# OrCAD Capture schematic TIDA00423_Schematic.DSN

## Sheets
1 PAGE2: size B; title: TIDA00423 High-Speed Front-End for PCIe Gen-3 Cards; rev: B; note: TIDA00423 Page 2
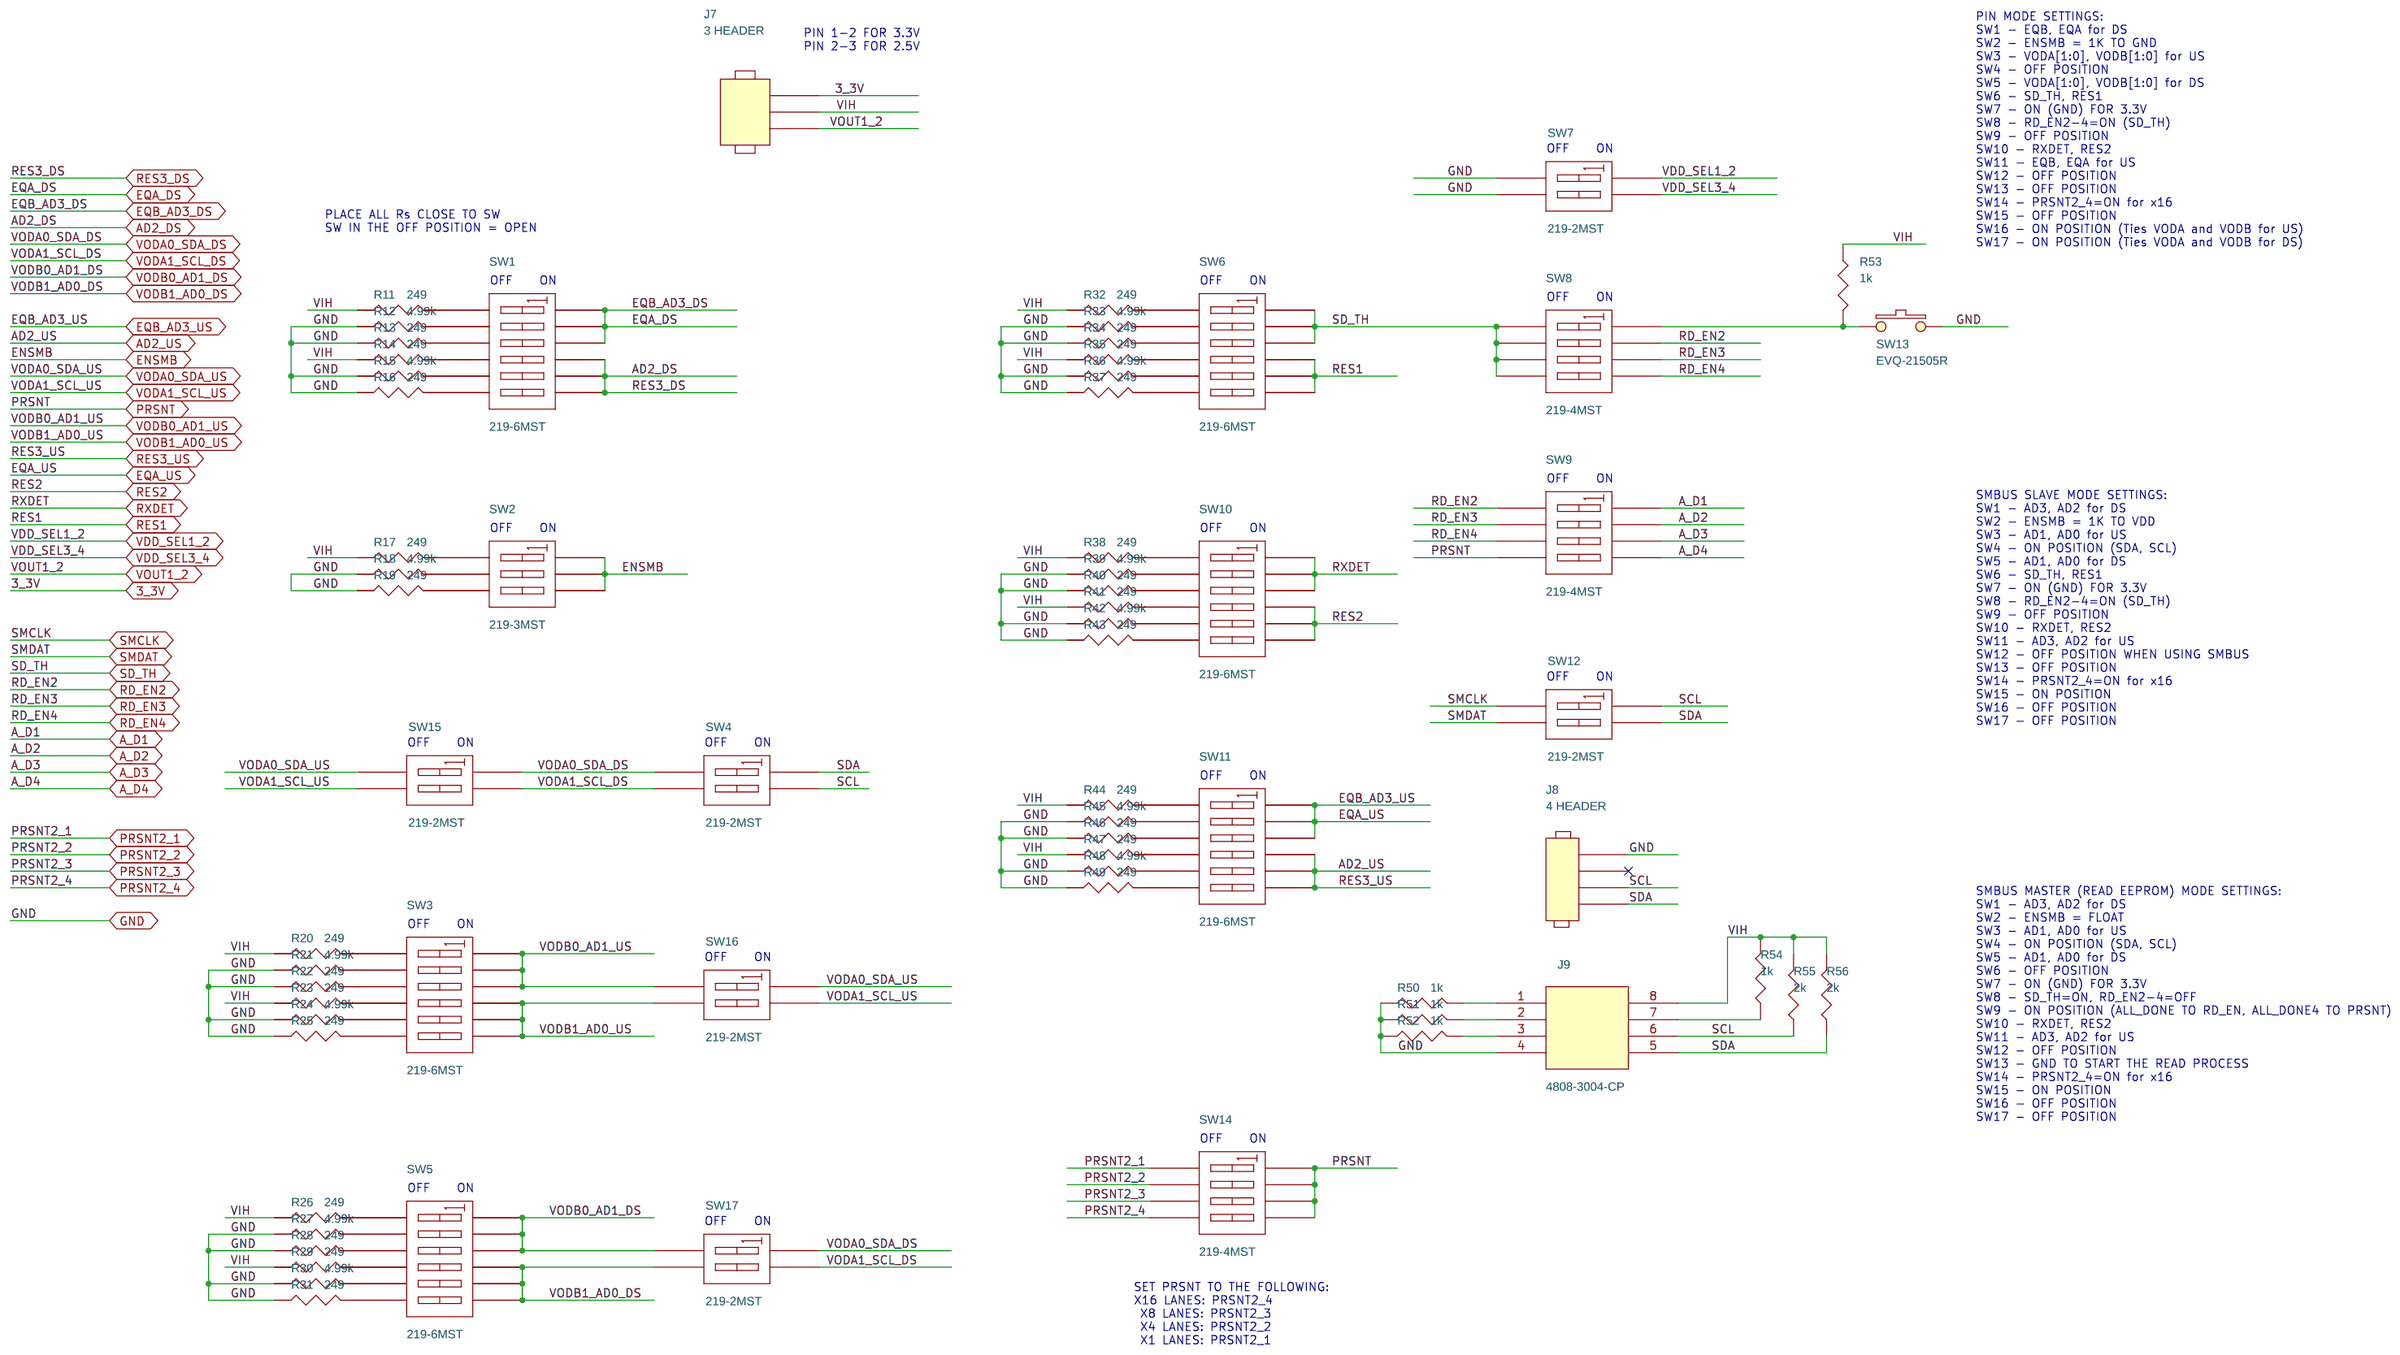
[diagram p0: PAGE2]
2 PAGE1: size B; note: TIDA00423 Page 1
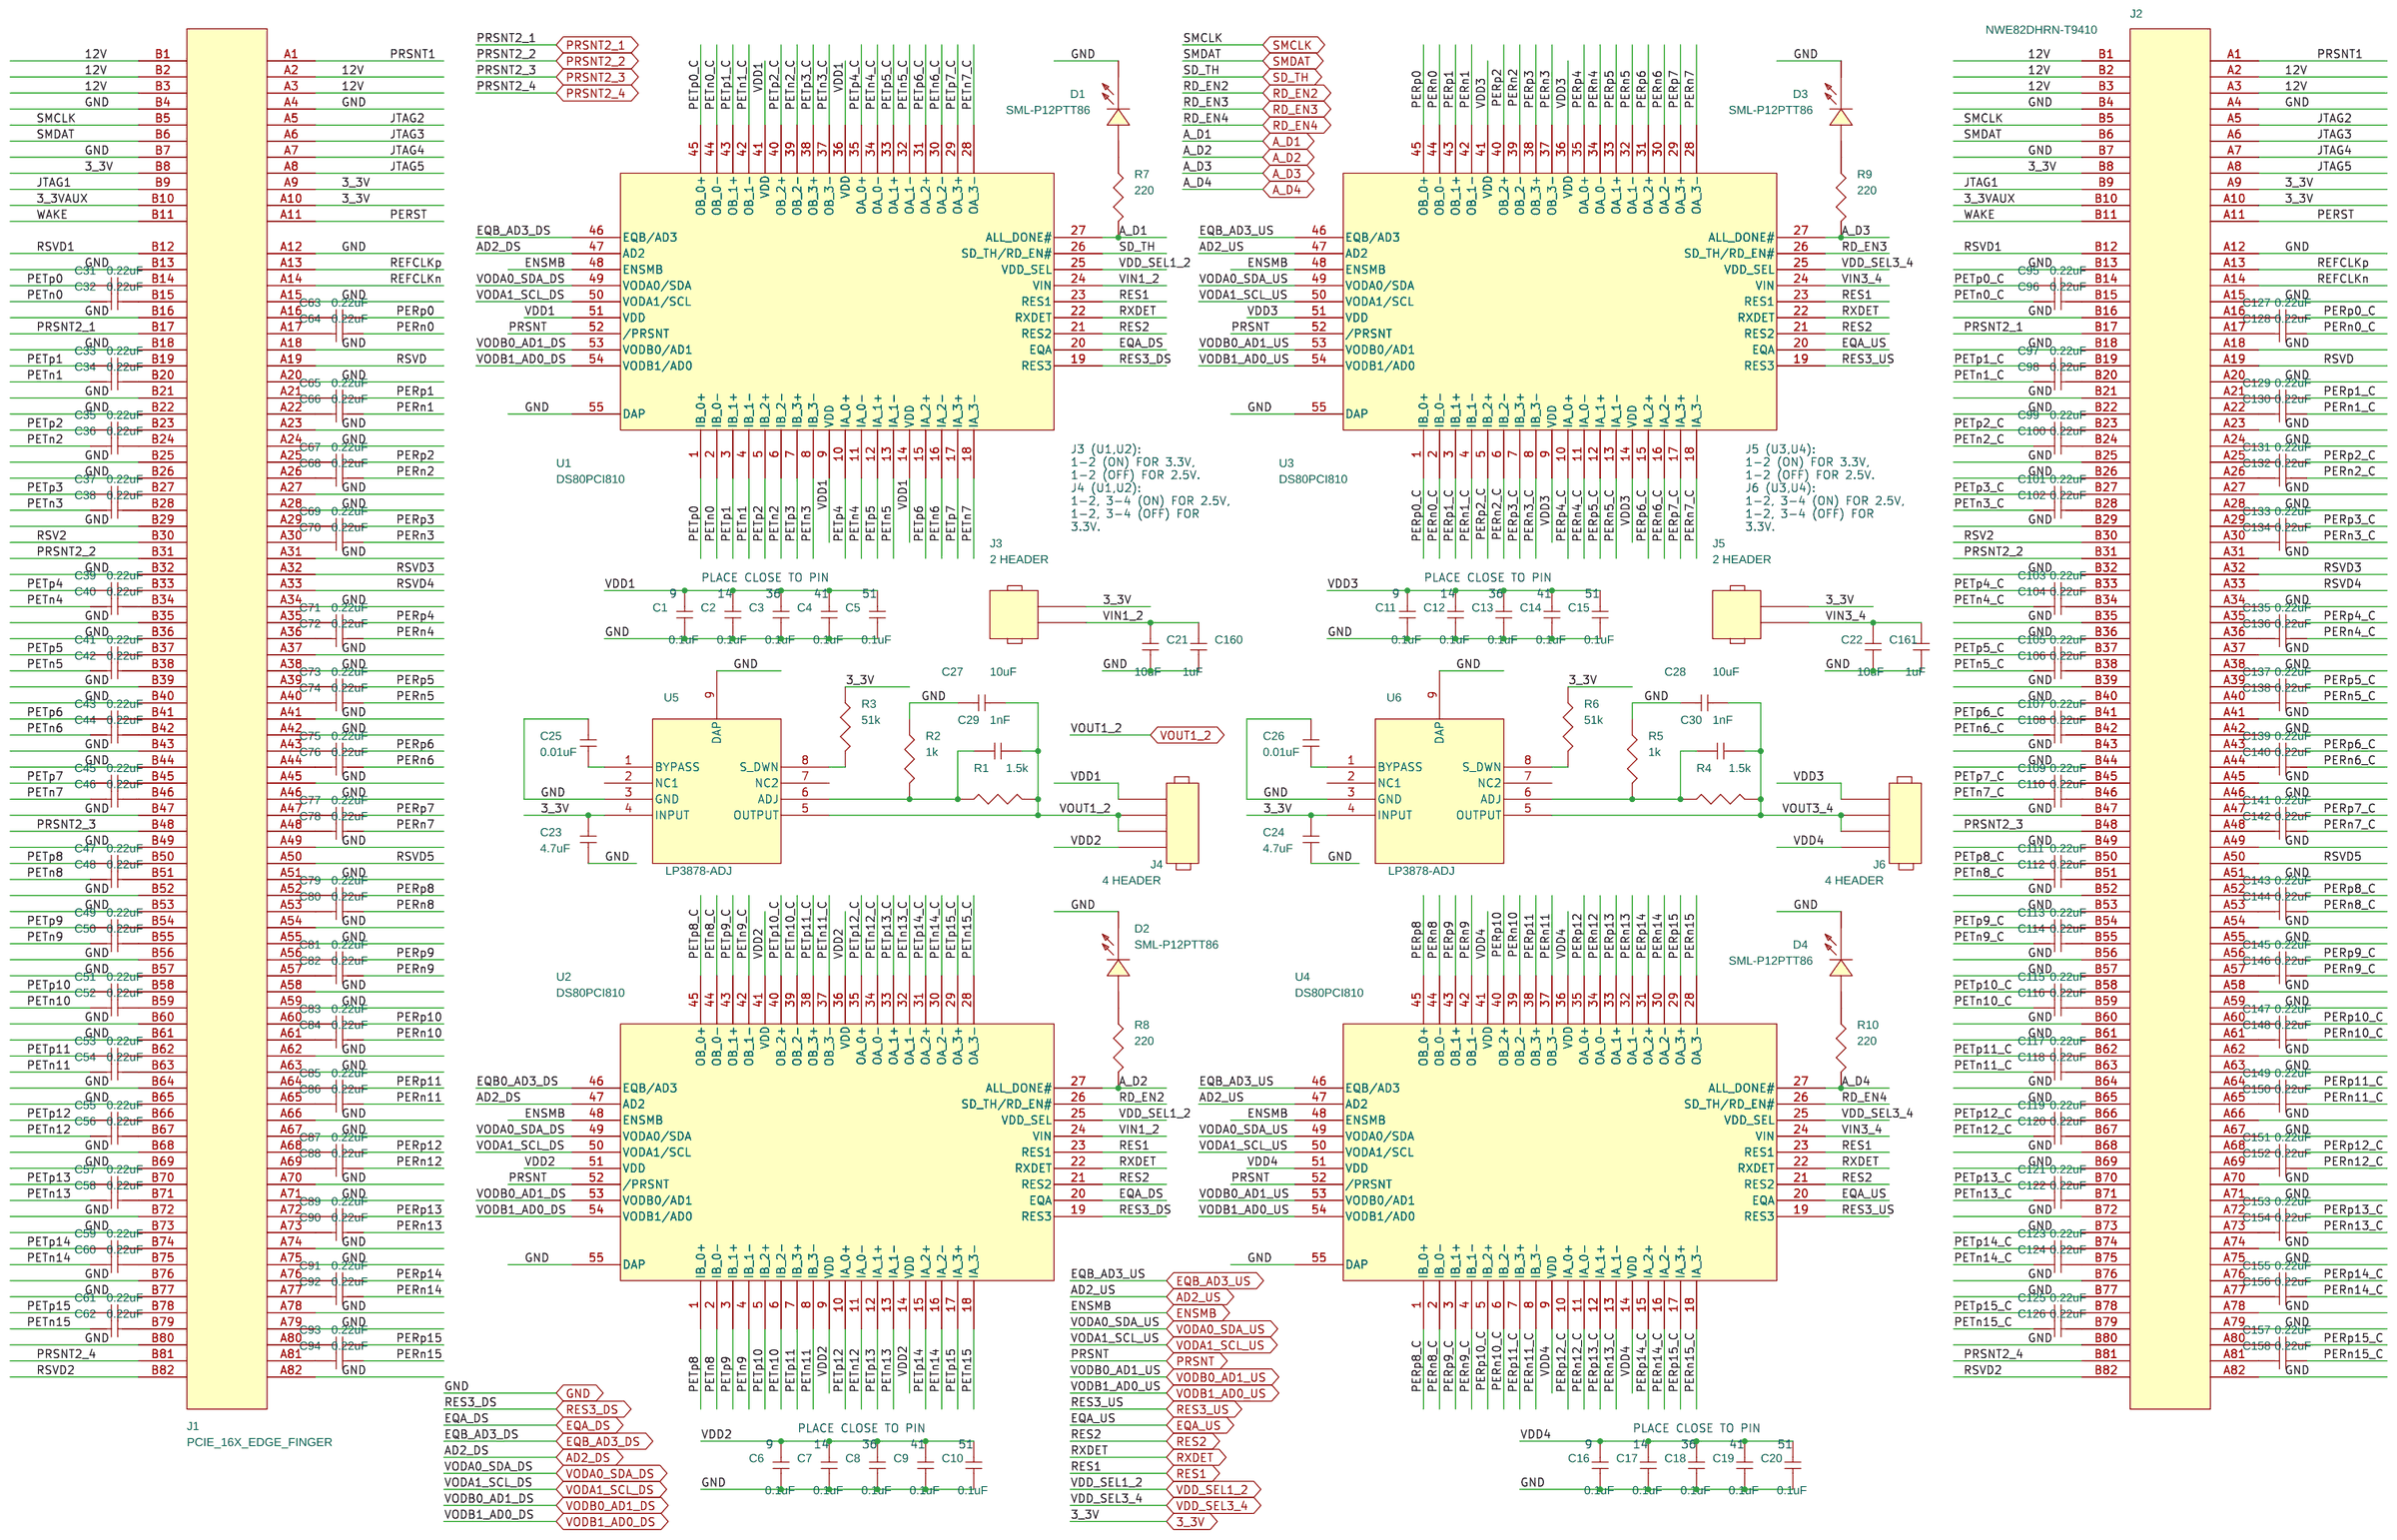
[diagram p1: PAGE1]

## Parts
sheet PAGE1
C1  0.1uF  [0201]
C2  0.1uF  [0201]
C3  0.1uF  [0201]
C4  0.1uF  [0201]
C5  0.1uF  [0201]
C6  0.1uF  [0201]
C7  0.1uF  [0201]
C8  0.1uF  [0201]
C9  0.1uF  [0201]
C10  0.1uF  [0201]
C11  0.1uF  [0201]
C12  0.1uF  [0201]
C13  0.1uF  [0201]
C14  0.1uF  [0201]
C15  0.1uF  [0201]
C16  0.1uF  [0201]
C17  0.1uF  [0201]
C18  0.1uF  [0201]
C19  0.1uF  [0201]
C20  0.1uF  [0201]
C21  10uF  [0603]
C22  10uF  [0603]
C23  4.7uF  [0402]
C24  4.7uF  [0402]
C25  0.01uF  [0402]
C26  0.01uF  [0402]
C27  10uF  [0603]
C28  10uF  [0603]
C29  1nF  [0201]
C30  1nF  [0201]
C31  0.22uF  [0201]
C32  0.22uF  [0201]
C33  0.22uF  [0201]
C34  0.22uF  [0201]
C35  0.22uF  [0201]
C36  0.22uF  [0201]
C37  0.22uF  [0201]
C38  0.22uF  [0201]
C39  0.22uF  [0201]
C40  0.22uF  [0201]
C41  0.22uF  [0201]
C42  0.22uF  [0201]
C43  0.22uF  [0201]
C44  0.22uF  [0201]
C45  0.22uF  [0201]
C46  0.22uF  [0201]
C47  0.22uF  [0201]
C48  0.22uF  [0201]
C49  0.22uF  [0201]
C50  0.22uF  [0201]
C51  0.22uF  [0201]
C52  0.22uF  [0201]
C53  0.22uF  [0201]
C54  0.22uF  [0201]
C55  0.22uF  [0201]
C56  0.22uF  [0201]
C57  0.22uF  [0201]
C58  0.22uF  [0201]
C59  0.22uF  [0201]
C60  0.22uF  [0201]
C61  0.22uF  [0201]
C62  0.22uF  [0201]
C63  0.22uF  [0201]
C64  0.22uF  [0201]
C65  0.22uF  [0201]
C66  0.22uF  [0201]
C67  0.22uF  [0201]
C68  0.22uF  [0201]
C69  0.22uF  [0201]
C70  0.22uF  [0201]
C71  0.22uF  [0201]
C72  0.22uF  [0201]
C73  0.22uF  [0201]
C74  0.22uF  [0201]
C75  0.22uF  [0201]
C76  0.22uF  [0201]
C77  0.22uF  [0201]
C78  0.22uF  [0201]
C79  0.22uF  [0201]
C80  0.22uF  [0201]
C81  0.22uF  [0201]
C82  0.22uF  [0201]
C83  0.22uF  [0201]
C84  0.22uF  [0201]
C85  0.22uF  [0201]
C86  0.22uF  [0201]
C87  0.22uF  [0201]
C88  0.22uF  [0201]
C89  0.22uF  [0201]
C90  0.22uF  [0201]
C91  0.22uF  [0201]
C92  0.22uF  [0201]
C93  0.22uF  [0201]
C94  0.22uF  [0201]
C95  0.22uF  [0201]
C96  0.22uF  [0201]
C97  0.22uF  [0201]
C98  0.22uF  [0201]
C99  0.22uF  [0201]
C100  0.22uF  [0201]
C101  0.22uF  [0201]
C102  0.22uF  [0201]
C103  0.22uF  [0201]
C104  0.22uF  [0201]
C105  0.22uF  [0201]
C106  0.22uF  [0201]
C107  0.22uF  [0201]
C108  0.22uF  [0201]
C109  0.22uF  [0201]
C110  0.22uF  [0201]
C111  0.22uF  [0201]
C112  0.22uF  [0201]
C113  0.22uF  [0201]
C114  0.22uF  [0201]
C115  0.22uF  [0201]
C116  0.22uF  [0201]
C117  0.22uF  [0201]
C118  0.22uF  [0201]
C119  0.22uF  [0201]
C120  0.22uF  [0201]
C121  0.22uF  [0201]
C122  0.22uF  [0201]
C123  0.22uF  [0201]
C124  0.22uF  [0201]
C125  0.22uF  [0201]
C126  0.22uF  [0201]
C127  0.22uF  [0201]
C128  0.22uF  [0201]
C129  0.22uF  [0201]
C130  0.22uF  [0201]
C131  0.22uF  [0201]
C132  0.22uF  [0201]
C133  0.22uF  [0201]
C134  0.22uF  [0201]
C135  0.22uF  [0201]
C136  0.22uF  [0201]
C137  0.22uF  [0201]
C138  0.22uF  [0201]
C139  0.22uF  [0201]
C140  0.22uF  [0201]
C141  0.22uF  [0201]
C142  0.22uF  [0201]
C143  0.22uF  [0201]
C144  0.22uF  [0201]
C145  0.22uF  [0201]
C146  0.22uF  [0201]
C147  0.22uF  [0201]
C148  0.22uF  [0201]
C149  0.22uF  [0201]
C150  0.22uF  [0201]
C151  0.22uF  [0201]
C152  0.22uF  [0201]
C153  0.22uF  [0201]
C154  0.22uF  [0201]
C155  0.22uF  [0201]
C156  0.22uF  [0201]
C157  0.22uF  [0201]
C158  0.22uF  [0201]
C160  1uF  [0402]
C161  1uF  [0402]
D1  SML-P12PTT86  [0402]
D2  SML-P12PTT86  [0402]
D3  SML-P12PTT86  [0402]
D4  SML-P12PTT86  [0402]
J1  PCIE_16X_EDGE_FINGER  [PCIE_16X_EDGE_FINGER]
J2  NWE82DHRN-T9410  [NWE82DHRN-T9410]
J3  2 HEADER  [2_HEADER]
J4  4 HEADER  [4_HEADER]
J5  2 HEADER  [2_HEADER]
J6  4 HEADER  [4_HEADER]
R1  1.5k  [0402]
R2  1k  [0402]
R3  51k  [0402]
R4  1.5k  [0402]
R5  1k  [0402]
R6  51k  [0402]
R7  220  [0402]
R8  220  [0402]
R9  220  [0402]
R10  220  [0402]
U1  DS80PCI810  [54_LLP]
U2  DS80PCI810  [54_LLP]
U3  DS80PCI810  [54_LLP]
U4  DS80PCI810  [54_LLP]
U5  LP3878-ADJ  [PSOP-8]
U6  LP3878-ADJ  [PSOP-8]
sheet PAGE2
J7  3 HEADER  [3_HEADER]
J8  4 HEADER  [4_HEADER]
J9  4808-3004-CP  [DIP8]
R11  249  [0402]
R12  4.99k  [0402]
R13  249  [0402]
R14  249  [0402]
R15  4.99k  [0402]
R16  249  [0402]
R17  249  [0402]
R18  4.99k  [0402]
R19  249  [0402]
R20  249  [0402]
R21  4.99k  [0402]
R22  249  [0402]
R23  249  [0402]
R24  4.99k  [0402]
R25  249  [0402]
R26  249  [0402]
R27  4.99k  [0402]
R28  249  [0402]
R29  249  [0402]
R30  4.99k  [0402]
R31  249  [0402]
R32  249  [0402]
R33  4.99k  [0402]
R34  249  [0402]
R35  249  [0402]
R36  4.99k  [0402]
R37  249  [0402]
R38  249  [0402]
R39  4.99k  [0402]
R40  249  [0402]
R41  249  [0402]
R42  4.99k  [0402]
R43  249  [0402]
R44  249  [0402]
R45  4.99k  [0402]
R46  249  [0402]
R47  249  [0402]
R48  4.99k  [0402]
R49  249  [0402]
R50  1k  [0402]
R51  1k  [0402]
R52  1k  [0402]
R53  1k  [0402]
R54  1k  [0402]
R55  2k  [0402]
R56  2k  [0402]
SW1  219-6MST  [219-6MST]
SW2  219-3MST  [219-3MST]
SW3  219-6MST  [219-6MST]
SW4  219-2MST  [219-2MST]
SW5  219-6MST  [219-6MST]
SW6  219-6MST  [219-6MST]
SW7  219-2MST  [219-2MST]
SW8  219-4MST  [219-4MST]
SW9  219-4MST  [219-4MST]
SW10  219-6MST  [219-6MST]
SW11  219-6MST  [219-6MST]
SW12  219-2MST  [219-2MST]
SW13  EVQ-21505R  [EVQ-21505R]
SW14  219-4MST  [219-4MST]
SW15  219-2MST  [219-2MST]
SW16  219-2MST  [219-2MST]
SW17  219-2MST  [219-2MST]

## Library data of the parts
C1-C158 = C_0
C160 C161 = C
D1-D4 = 1091QM_0
J1 = PCIE_16X_EDGE_FINGER
J2 = NWE82DHRN-T9410
J3 J5 = HEADER_2
J4 J6 J8 = 4_HEADER
R1-R6 R53-R56 = RESISTOR_SM
R7-R10 = R_0: Power: 1/16W; Tolerance: 5%
U1-U4 = DS80PCI800_0
U5 U6 = LP3878-ADJ_0
J7 = HEADER_3
J9 = DIP8_SOCKET
R11-R52 = RESISTOR
SW1 SW3 SW5 SW6 SW10 SW11 = SW_DIP-6_SM
SW2 = SW_DIP-3_SM
SW4 SW7 SW12 SW15-SW17 = SW_DIP-2_SM
SW8 SW9 SW14 = SW_DIP-4_SM
SW13 = SW_PUSHBUTTON-SPST

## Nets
12V: J1.A2 J1.A3 J1.B1 J1.B2 J1.B3 J2.A2 J2.A3 J2.B1 J2.B2 J2.B3
GND: C1.1 C2.1 C3.1 C4.1 C5.1 C6.1 C7.1 C8.1 C9.1 C10.1 C11.1 C12.1 C13.1 C14.1 C15.1 C16.1 C17.1 C18.1 C19.1 C20.1 C21.1 C22.1 C23.1 C24.1 C25.2 C26.2 C27.2 C28.2 C160.1 C161.1 D1.1(CATHODE) D2.1(CATHODE) D3.1(CATHODE) D4.1(CATHODE) J1.A4 J1.A12 J1.A15 J1.A18 J1.A20 J1.A23 J1.A24 J1.A27 J1.A28 J1.A31 J1.A34 J1.A37 J1.A38 J1.A41 J1.A42 J1.A45 J1.A46 J1.A49 J1.A51 J1.A54 J1.A55 J1.A58 J1.A59 J1.A62 J1.A63 J1.A66 J1.A67 J1.A70 J1.A71 J1.A74 J1.A75 J1.A78 J1.A79 J1.A82 J1.B4 J1.B7 J1.B13 J1.B16 J1.B18 J1.B21 J1.B22 J1.B25 J1.B26 J1.B29 J1.B32 J1.B35 J1.B36 J1.B39 J1.B40 J1.B43 J1.B44 J1.B47 J1.B49 J1.B52 J1.B53 J1.B56 J1.B57 J1.B60 J1.B61 J1.B64 J1.B65 J1.B68 J1.B69 J1.B72 J1.B73 J1.B76 J1.B77 J1.B80 J2.A4 J2.A12 J2.A15 J2.A18 J2.A20 J2.A23 J2.A24 J2.A27 J2.A28 J2.A31 J2.A34 J2.A37 J2.A38 J2.A41 J2.A42 J2.A45 J2.A46 J2.A49 J2.A51 J2.A54 J2.A55 J2.A58 J2.A59 J2.A62 J2.A63 J2.A66 J2.A67 J2.A70 J2.A71 J2.A74 J2.A75 J2.A78 J2.A79 J2.A82 J2.B4 J2.B7 J2.B13 J2.B16 J2.B18 J2.B21 J2.B22 J2.B25 J2.B26 J2.B29 J2.B32 J2.B35 J2.B36 J2.B39 J2.B40 J2.B43 J2.B44 J2.B47 J2.B49 J2.B52 J2.B53 J2.B56 J2.B57 J2.B60 J2.B61 J2.B64 J2.B65 J2.B68 J2.B69 J2.B72 J2.B73 J2.B76 J2.B77 J2.B80 J8.1 J9.4 R2.1 R5.1 R12.1 R13.1 R15.1 R16.1 R18.1 R19.1 R21.1 R22.1 R24.1 R25.1 R27.1 R28.1 R30.1 R31.1 R33.1 R34.1 R36.1 R37.1 R39.1 R40.1 R42.1 R43.1 R45.1 R46.1 R48.1 R49.1 R50.1 R51.1 R52.1 SW7.1(A1) SW7.2(A2) SW13.2 U1.55(DAP) U2.55(DAP) U3.55(DAP) U4.55(DAP) U5.3(GND) U5.9(DAP) U6.3(GND) U6.9(DAP)
VDD1: C1.2 C2.2 C3.2 C4.2 C5.2 J4.1 U1.9(VDD) U1.14(VDD) U1.36(VDD) U1.41(VDD) U1.51(VDD)
VDD2: C6.2 C7.2 C8.2 C9.2 C10.2 J4.4 U2.9(VDD) U2.14(VDD) U2.36(VDD) U2.41(VDD) U2.51(VDD)
VDD3: C11.2 C12.2 C13.2 C14.2 C15.2 J6.1 U3.9(VDD) U3.14(VDD) U3.36(VDD) U3.41(VDD) U3.51(VDD)
VDD4: C16.2 C17.2 C18.2 C19.2 C20.2 J6.4 U4.9(VDD) U4.14(VDD) U4.36(VDD) U4.41(VDD) U4.51(VDD)
VDD_SEL1_2: SW7.4(B1) U1.25(VDD_SEL) U2.25(VDD_SEL)
VDD_SEL3_4: SW7.3(B2) U3.25(VDD_SEL) U4.25(VDD_SEL)
VIN1_2: C21.2 C160.2 J3.2 U1.24(VIN) U2.24(VIN)
VIN3_4: C22.2 C161.2 J5.2 U3.24(VIN) U4.24(VIN)
3_3V: C23.2 C24.2 J1.A9 J1.A10 J1.B8 J2.A9 J2.A10 J2.B8 J3.1 J5.1 J7.1 R3.1 R6.1 U5.4(INPUT) U6.4(INPUT)
3_3VAUX: J1.B10 J2.B10
A_D1: R7.2 SW9.8(B1) U1.27(ALL_DONE#)
A_D2: R8.2 SW9.7(B2) U2.27(ALL_DONE#)
A_D3: R9.2 SW9.6(B3) U3.27(ALL_DONE#)
A_D4: R10.2 SW9.5(B4) U4.27(ALL_DONE#)
AD2_DS: SW1.7(B6) SW1.8(B5) SW1.9(B4) U1.19(RES3) U1.47(AD2) U2.19(RES3) U2.47(AD2)
AD2_US: SW11.7(B6) SW11.8(B5) SW11.9(B4) U3.19(RES3) U3.47(AD2) U4.19(RES3) U4.47(AD2)
ENSMB: SW2.4(B3) SW2.5(B2) SW2.6(B1) U1.48(ENSMB) U2.48(ENSMB) U3.48(ENSMB) U4.48(ENSMB)
EQA_DS: SW1.10(B3) SW1.11(B2) SW1.12(B1) U1.20(EQA) U1.46(EQB/AD3) U2.20(EQA)
EQA_US: SW11.10(B3) SW11.11(B2) SW11.12(B1) U3.20(EQA) U3.46(EQB/AD3) U4.20(EQA) U4.46(EQB/AD3)
EQB0_AD3_DS: U2.46(EQB/AD3)
JTAG1: J1.B9 J2.B9
JTAG2: J1.A5 J2.A5
JTAG3: J1.A6 J2.A6
JTAG4: J1.A7 J2.A7
JTAG5: J1.A8 J2.A8
PERn0: C64.1 U3.44(OB_0-)
PERn0_C: C128.1 U3.2(IB_0-)
PERn1: C66.1 U3.42(OB_1-)
PERn1_C: C130.1 U3.4(IB_1-)
PERn2: C68.1 U3.39(OB_2-)
PERn2_C: C132.1 U3.6(IB_2-)
PERn3: C70.1 U3.37(OB_3-)
PERn3_C: C134.1 U3.8(IB_3-)
PERn4: C72.1 U3.34(OA_0-)
PERn4_C: C136.1 U3.11(IA_0-)
PERn5: C74.1 U3.32(OA_1-)
PERn5_C: C138.1 U3.13(IA_1-)
PERn6: C76.1 U3.30(OA_2-)
PERn6_C: C140.1 U3.16(IA_2-)
PERn7: C78.1 U3.28(OA_3-)
PERn7_C: C142.1 U3.18(IA_3-)
PERn8: C80.1 U4.44(OB_0-)
PERn8_C: C144.1 U4.2(IB_0-)
PERn9: C82.1 U4.42(OB_1-)
PERn9_C: C146.1 U4.4(IB_1-)
PERn10: C84.1 U4.39(OB_2-)
PERn10_C: C148.1 U4.6(IB_2-)
PERn11: C86.1 U4.37(OB_3-)
PERn11_C: C150.1 U4.8(IB_3-)
PERn12: C88.1 U4.34(OA_0-)
PERn12_C: C152.1 U4.11(IA_0-)
PERn13: C90.1 U4.32(OA_1-)
PERn13_C: C154.1 U4.13(IA_1-)
PERn14: C92.1 U4.30(OA_2-)
PERn14_C: C156.1 U4.16(IA_2-)
PERn15: C94.1 U4.28(OA_3-)
PERn15_C: C158.1 U4.18(IA_3-)
PERp0: C63.1 U3.45(OB_0+)
PERp0_C: C127.1 U3.1(IB_0+)
PERp1: C65.1 U3.43(OB_1+)
PERp1_C: C129.1 U3.3(IB_1+)
PERp2: C67.1 U3.40(OB_2+)
PERp2_C: C131.1 U3.5(IB_2+)
PERp3: C69.1 U3.38(OB_3+)
PERp3_C: C133.1 U3.7(IB_3+)
PERp4: C71.1 U3.35(OA_0+)
PERp4_C: C135.1 U3.10(IA_0+)
PERp5: C73.1 U3.33(OA_1+)
PERp5_C: C137.1 U3.12(IA_1+)
PERp6: C75.1 U3.31(OA_2+)
PERp6_C: C139.1 U3.15(IA_2+)
PERp7: C77.1 U3.29(OA_3+)
PERp7_C: C141.1 U3.17(IA_3+)
PERp8: C79.1 U4.45(OB_0+)
PERp8_C: C143.1 U4.1(IB_0+)
PERp9: C81.1 U4.43(OB_1+)
PERp9_C: C145.1 U4.3(IB_1+)
PERp10: C83.1 U4.40(OB_2+)
PERp10_C: C147.1 U4.5(IB_2+)
PERp11: C85.1 U4.38(OB_3+)
PERp11_C: C149.1 U4.7(IB_3+)
PERp12: C87.1 U4.35(OA_0+)
PERp12_C: C151.1 U4.10(IA_0+)
PERp13: C89.1 U4.33(OA_1+)
PERp13_C: C153.1 U4.12(IA_1+)
PERp14: C91.1 U4.31(OA_2+)
PERp14_C: C155.1 U4.15(IA_2+)
PERp15: C93.1 U4.29(OA_3+)
PERp15_C: C157.1 U4.17(IA_3+)
PERST: J1.A11 J2.A11
PETn0: C32.2 U1.2(IB_0-)
PETn0_C: C96.2 U1.44(OB_0-)
PETn1: C34.2 U1.4(IB_1-)
PETn1_C: C98.2 U1.42(OB_1-)
PETn2: C36.2 U1.6(IB_2-)
PETn2_C: C100.2 U1.39(OB_2-)
PETn3: C38.2 U1.8(IB_3-)
PETn3_C: C102.2 U1.37(OB_3-)
PETn4: C40.2 U1.11(IA_0-)
PETn4_C: C104.2 U1.34(OA_0-)
PETn5: C42.2 U1.13(IA_1-)
PETn5_C: C106.2 U1.32(OA_1-)
PETn6: C44.2 U1.16(IA_2-)
PETn6_C: C108.2 U1.30(OA_2-)
PETn7: C46.2 U1.18(IA_3-)
PETn7_C: C110.2 U1.28(OA_3-)
PETn8: C48.2 U2.2(IB_0-)
PETn8_C: C112.2 U2.44(OB_0-)
PETn9: C50.2 U2.4(IB_1-)
PETn9_C: C114.2 U2.42(OB_1-)
PETn10: C52.2 U2.6(IB_2-)
PETn10_C: C116.2 U2.39(OB_2-)
PETn11: C54.2 U2.8(IB_3-)
PETn11_C: C118.2 U2.37(OB_3-)
PETn12: C56.2 U2.11(IA_0-)
PETn12_C: C120.2 U2.34(OA_0-)
PETn13: C58.2 U2.13(IA_1-)
PETn13_C: C122.2 U2.32(OA_1-)
PETn14: C60.2 U2.16(IA_2-)
PETn14_C: C124.2 U2.30(OA_2-)
PETn15: C62.2 U2.18(IA_3-)
PETn15_C: C126.2 U2.28(OA_3-)
PETp0: C31.2 U1.1(IB_0+)
PETp0_C: C95.2 U1.45(OB_0+)
PETp1: C33.2 U1.3(IB_1+)
PETp1_C: C97.2 U1.43(OB_1+)
PETp2: C35.2 U1.5(IB_2+)
PETp2_C: C99.2 U1.40(OB_2+)
PETp3: C37.2 U1.7(IB_3+)
PETp3_C: C101.2 U1.38(OB_3+)
PETp4: C39.2 U1.10(IA_0+)
PETp4_C: C103.2 U1.35(OA_0+)
PETp5: C41.2 U1.12(IA_1+)
PETp5_C: C105.2 U1.33(OA_1+)
PETp6: C43.2 U1.15(IA_2+)
PETp6_C: C107.2 U1.31(OA_2+)
PETp7: C45.2 U1.17(IA_3+)
PETp7_C: C109.2 U1.29(OA_3+)
PETp8: C47.2 U2.1(IB_0+)
PETp8_C: C111.2 U2.45(OB_0+)
PETp9: C49.2 U2.3(IB_1+)
PETp9_C: C113.2 U2.43(OB_1+)
PETp10: C51.2 U2.5(IB_2+)
PETp10_C: C115.2 U2.40(OB_2+)
PETp11: C53.2 U2.7(IB_3+)
PETp11_C: C117.2 U2.38(OB_3+)
PETp12: C55.2 U2.10(IA_0+)
PETp12_C: C119.2 U2.35(OA_0+)
PETp13: C57.2 U2.12(IA_1+)
PETp13_C: C121.2 U2.33(OA_1+)
PETp14: C59.2 U2.15(IA_2+)
PETp14_C: C123.2 U2.31(OA_2+)
PETp15: C61.2 U2.17(IA_3+)
PETp15_C: C125.2 U2.29(OA_3+)
PRSNT: SW9.4(A4) SW14.5(B4) SW14.6(B3) SW14.7(B2) SW14.8(B1) U1.52(/PRSNT) U2.52(/PRSNT) U3.52(/PRSNT) U4.52(/PRSNT)
PRSNT1: J1.A1 J2.A1
PRSNT2_1: J1.B17 J2.B17 SW14.1(A1)
PRSNT2_2: J1.B31 J2.B31 SW14.2(A2)
PRSNT2_3: J1.B48 J2.B48 SW14.3(A3)
PRSNT2_4: J1.B81 J2.B81 SW14.4(A4)
RD_EN2: SW8.7(B2) SW9.1(A1) U2.26(SD_TH/RD_EN#)
RD_EN3: SW8.6(B3) SW9.2(A2) U3.26(SD_TH/RD_EN#)
RD_EN4: SW8.5(B4) SW9.3(A3) U4.26(SD_TH/RD_EN#)
REFCLKn: J1.A14 J2.A14
REFCLKp: J1.A13 J2.A13
RES1: SW6.7(B6) SW6.8(B5) SW6.9(B4) U1.23(RES1) U2.23(RES1) U3.23(RES1) U4.23(RES1)
RES2: SW10.7(B6) SW10.8(B5) SW10.9(B4) U1.21(RES2) U2.21(RES2) U3.21(RES2) U4.21(RES2)
RSV2: J1.B30 J2.B30
RSVD: J1.A19 J2.A19
RSVD1: J1.B12 J2.B12
RSVD2: J1.B82 J2.B82
RSVD3: J1.A32 J2.A32
RSVD4: J1.A33 J2.A33
RSVD5: J1.A50 J2.A50
RXDET: SW10.10(B3) SW10.11(B2) SW10.12(B1) U1.22(RXDET) U2.22(RXDET) U3.22(RXDET) U4.22(RXDET)
SCL: J8.3 J9.6 R55.1 SW4.3(B2) SW12.4(B1)
SD_TH: SW6.10(B3) SW6.11(B2) SW6.12(B1) SW8.1(A1) SW8.2(A2) SW8.3(A3) SW8.4(A4) U1.26(SD_TH/RD_EN#)
SDA: J8.4 J9.5 R56.1 SW4.4(B1) SW12.3(B2)
SMCLK: J1.B5 J2.B5 SW12.1(A1)
SMDAT: J1.B6 J2.B6 SW12.2(A2)
VIH: J7.2 J9.8 R11.1 R14.1 R17.1 R20.1 R23.1 R26.1 R29.1 R32.1 R35.1 R38.1 R41.1 R44.1 R47.1 R53.1 R54.2 R55.2 R56.2
VODA0_SDA_DS: SW4.1(A1) SW15.4(B1) SW17.4(B1) U1.49(VODA0/SDA) U2.49(VODA0/SDA)
VODA0_SDA_US: SW15.1(A1) SW16.4(B1) U3.49(VODA0/SDA) U4.49(VODA0/SDA)
VODA1_SCL_DS: SW4.2(A2) SW15.3(B2) SW17.3(B2) U1.50(VODA1/SCL) U2.50(VODA1/SCL)
VODA1_SCL_US: SW15.2(A2) SW16.3(B2) U3.50(VODA1/SCL) U4.50(VODA1/SCL)
VODB0_AD1_DS: SW5.10(B3) SW5.11(B2) SW5.12(B1) SW17.1(A1) U1.53(VODB0/AD1) U2.53(VODB0/AD1)
VODB0_AD1_US: SW3.10(B3) SW3.11(B2) SW3.12(B1) SW16.1(A1) U3.53(VODB0/AD1) U4.53(VODB0/AD1)
VODB1_AD0_DS: SW5.7(B6) SW5.8(B5) SW5.9(B4) SW17.2(A2) U1.54(VODB1/AD0) U2.54(VODB1/AD0)
VODB1_AD0_US: SW3.7(B6) SW3.8(B5) SW3.9(B4) SW16.2(A2) U3.54(VODB1/AD0) U4.54(VODB1/AD0)
VOUT1_2: C27.1 C29.1 J4.2 J4.3 J7.3 R1.2 U5.5(OUTPUT)
VOUT3_4: C28.1 C30.1 J6.2 J6.3 R4.2 U6.5(OUTPUT)
WAKE: J1.B11 J2.B11
N14347575: C29.2 R1.1 R2.2 U5.6(ADJ)
N14347651: C25.1 U5.1(BYPASS)
N14347847: R3.2 U5.8(S_DWN)
N14379250: C26.1 U6.1(BYPASS)
N14379574: C30.2 R4.1 R5.2 U6.6(ADJ)
N14379914: R6.2 U6.8(S_DWN)
N14519010: R53.2 SW8.8(B1) SW13.1
N14524358: J9.3 R52.2
N14524360: J9.2 R51.2
N14524362: J9.1 R50.2
N14693554: J9.7 R54.1
N14835916: C152.2 J2.A69
N14835917: C124.1 J2.B75
N14835918: C117.1 J2.B62
N14835919: C101.1 J2.B27
N14835920: C151.2 J2.A68
N14835921: C126.1 J2.B79
N14835922: C116.1 J2.B59
N14835923: C125.1 J2.B78
N14835924: C33.1 J1.B19
N14835925: C150.2 J2.A65
N14835926: C149.2 J2.A64
N14835927: C139.2 J2.A43
N14835928: C51.1 J1.B58
N14835929: C94.2 J1.A81
N14835930: C127.2 J2.A16
N14835931: C123.1 J2.B74
N14835932: C47.1 J1.B50
N14835933: C93.2 J1.A80
N14835934: C78.2 J1.A48
N14835935: C36.1 J1.B24
N14835936: C95.1 J2.B14
N14835937: C76.2 J1.A44
N14835938: C148.2 J2.A61
N14835939: C147.2 J2.A60
N14835940: C90.2 J1.A73
N14835941: C122.1 J2.B71
N14835942: C92.2 J1.A77
N14835943: C91.2 J1.A76
N14835944: C75.2 J1.A43
N14835945: C146.2 J2.A57
N14835946: D1.2(ANODE) R7.1
N14835947: C52.1 J1.B59
N14835948: C121.1 J2.B70
N14835949: C145.2 J2.A56
N14835950: C64.2 J1.A17
N14835951: C85.2 J1.A64
N14835952: C98.1 J2.B20
N14835953: C89.2 J1.A72
N14835954: C97.1 J2.B19
N14835955: C32.1 J1.B15
N14835956: C62.1 J1.B79
N14835957: C72.2 J1.A36
N14835958: C61.1 J1.B78
N14835959: C73.2 J1.A39
N14835960: C69.2 J1.A29
N14835961: C96.1 J2.B15
N14835962: C68.2 J1.A26
N14835963: C128.2 J2.A17
N14835964: C88.2 J1.A69
N14835965: C67.2 J1.A25
N14835966: C108.1 J2.B42
N14835967: C132.2 J2.A26
N14835968: C38.1 J1.B28
N14835969: C58.1 J1.B71
N14835970: C142.2 J2.A48
N14835971: C66.2 J1.A22
N14835972: C81.2 J1.A56
N14835973: D4.2(ANODE) R10.1
N14835974: C37.1 J1.B27
N14835975: C105.1 J2.B37
N14835976: C65.2 J1.A21
N14835977: C82.2 J1.A57
N14835978: D2.2(ANODE) R8.1
N14835979: C35.1 J1.B23
N14835980: C39.1 J1.B33
N14835981: C42.1 J1.B38
N14835982: C100.1 J2.B24
N14835983: C31.1 J1.B14
N14835984: C63.2 J1.A16
N14835985: C111.1 J2.B50
N14835986: C34.1 J1.B20
N14835987: C50.1 J1.B55
N14835988: D3.2(ANODE) R9.1
N14835989: C158.2 J2.A81
N14835990: C45.1 J1.B45
N14835991: C157.2 J2.A80
N14835992: C55.1 J1.B66
N14835993: C118.1 J2.B63
N14835994: C134.2 J2.A30
N14835995: C107.1 J2.B41
N14835996: C86.2 J1.A65
N14835997: C133.2 J2.A29
N14835998: C137.2 J2.A39
N14835999: C109.1 J2.B45
N14836000: C106.1 J2.B38
N14836001: C71.2 J1.A35
N14836002: C77.2 J1.A47
N14836003: C103.1 J2.B33
N14836004: C131.2 J2.A25
N14836005: C48.1 J1.B51
N14836006: C104.1 J2.B34
N14836007: C130.2 J2.A22
N14836008: C41.1 J1.B37
N14836009: C129.2 J2.A21
N14836010: C56.1 J1.B67
N14836011: C74.2 J1.A40
N14836012: C53.1 J1.B62
N14836013: C46.1 J1.B46
N14836014: C99.1 J2.B23
N14836015: C102.1 J2.B28
N14836016: C44.1 J1.B42
N14836017: C119.1 J2.B66
N14836018: C43.1 J1.B41
N14836019: C79.2 J1.A52
N14836020: C87.2 J1.A68
N14836021: C143.2 J2.A52
N14836022: C120.1 J2.B67
N14836023: C144.2 J2.A53
N14836024: C40.1 J1.B34
N14836025: C70.2 J1.A30
N14836026: C83.2 J1.A60
N14836027: C155.2 J2.A76
N14836028: C110.1 J2.B46
N14836029: C60.1 J1.B75
N14836030: C112.1 J2.B51
N14836031: C59.1 J1.B74
N14836032: C54.1 J1.B63
N14836033: C136.2 J2.A36
N14836034: C141.2 J2.A47
N14836035: C115.1 J2.B58
N14836036: C80.2 J1.A53
N14836037: C153.2 J2.A72
N14836038: C57.1 J1.B70
N14836039: C140.2 J2.A44
N14836040: C114.1 J2.B55
N14836041: C113.1 J2.B54
N14836042: C84.2 J1.A61
N14836043: C135.2 J2.A35
N14836044: C138.2 J2.A40
N14836045: C156.2 J2.A77
N14836046: C154.2 J2.A73
N14836047: C49.1 J1.B54
N14836709: R25.2 SW3.6(A6)
N14836710: R18.2 SW2.2(A2)
N14836711: R31.2 SW5.6(A6)
N14836712: R43.2 SW10.6(A6)
N14836713: R30.2 SW5.5(A5)
N14836714: R29.2 SW5.4(A4)
N14836715: R47.2 SW11.4(A4)
N14836716: R22.2 SW3.3(A3)
N14836717: R28.2 SW5.3(A3)
N14836718: R27.2 SW5.2(A2)
N14836719: R26.2 SW5.1(A1)
N14836720: R42.2 SW10.5(A5)
N14836721: R39.2 SW10.2(A2)
N14836722: R41.2 SW10.4(A4)
N14836723: R40.2 SW10.3(A3)
N14836724: R38.2 SW10.1(A1)
N14836725: R35.2 SW6.4(A4)
N14836726: R14.2 SW1.4(A4)
N14836727: R20.2 SW3.1(A1)
N14836728: R48.2 SW11.5(A5)
N14836729: R19.2 SW2.3(A3)
N14836730: R33.2 SW6.2(A2)
N14836731: R16.2 SW1.6(A6)
N14836732: R32.2 SW6.1(A1)
N14836733: R15.2 SW1.5(A5)
N14836734: R13.2 SW1.3(A3)
N14836735: R11.2 SW1.1(A1)
N14836736: R12.2 SW1.2(A2)
N14836737: R44.2 SW11.1(A1)
N14836738: R21.2 SW3.2(A2)
N14836739: R49.2 SW11.6(A6)
N14836740: R17.2 SW2.1(A1)
N14836741: R46.2 SW11.3(A3)
N14836742: R23.2 SW3.4(A4)
N14836743: R45.2 SW11.2(A2)
N14836744: R37.2 SW6.6(A6)
N14836745: R36.2 SW6.5(A5)
N14836746: R34.2 SW6.3(A3)
N14836747: R24.2 SW3.5(A5)

Not connected (* = marked no-connect by the designer): J8 2*; U5 2(NC1) 7(NC2); U6 2(NC1) 7(NC2)

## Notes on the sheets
sheet 1
- PIN MODE SETTINGS:
  SW1 - EQB, EQA for DS
  SW2 - ENSMB = 1K TO GND
  SW3 - VODA[1:0], VODB[1:0] for US
  SW4 - OFF POSITION
  SW5 - VODA[1:0], VODB[1:0] for DS
  SW6 - SD_TH, RES1
  SW7 - ON (GND) FOR 3.3V
  SW8 - RD_EN2-4=ON (SD_TH)
  SW9 - OFF POSITION
  SW10 - RXDET, RES2
  SW11 - EQB, EQA for US
  SW12 - OFF POSITION
  SW13 - OFF POSITION
  SW14 - PRSNT2_4=ON for x16
  SW15 - OFF POSITION
  SW16 - ON POSITION (Ties VODA and VODB for US)
  SW17 - ON POSITION (Ties VODA and VODB for DS)
- PIN 1-2 FOR 3.3V
  PIN 2-3 FOR 2.5V
- OFF
- ON
- PLACE ALL Rs CLOSE TO SW
  SW IN THE OFF POSITION = OPEN
- OFF
- ON
- OFF
- ON
- OFF
- ON
- OFF
- ON
- SMBUS SLAVE MODE SETTINGS:
  SW1 - AD3, AD2 for DS
  SW2 - ENSMB = 1K TO VDD
  SW3 - AD1, AD0 for US
  SW4 - ON POSITION (SDA, SCL)
  SW5 - AD1, AD0 for DS
  SW6 - SD_TH, RES1
  SW7 - ON (GND) FOR 3.3V
  SW8 - RD_EN2-4=ON (SD_TH)
  SW9 - OFF POSITION
  SW10 - RXDET, RES2
  SW11 - AD3, AD2 for US
  SW12 - OFF POSITION WHEN USING SMBUS
  SW13 - OFF POSITION
  SW14 - PRSNT2_4=ON for x16
  SW15 - ON POSITION
  SW16 - OFF POSITION
  SW17 - OFF POSITION
- OFF
- ON
- OFF
- ON
- OFF
- ON
- OFF
- ON
- OFF
- ON
- OFF
- ON
- SMBUS MASTER (READ EEPROM) MODE SETTINGS:
  SW1 - AD3, AD2 for DS
  SW2 - ENSMB = FLOAT
  SW3 - AD1, AD0 for US
  SW4 - ON POSITION (SDA, SCL)
  SW5 - AD1, AD0 for DS
  SW6 - OFF POSITION
  SW7 - ON (GND) FOR 3.3V
  SW8 - SD_TH=ON, RD_EN2-4=OFF
  SW9 - ON POSITION (ALL_DONE TO RD_EN, ALL_DONE4 TO PRSNT)
  SW10 - RXDET, RES2
  SW11 - AD3, AD2 for US
  SW12 - OFF POSITION
  SW13 - GND TO START THE READ PROCESS
  SW14 - PRSNT2_4=ON for x16
  SW15 - ON POSITION
  SW16 - OFF POSITION
  SW17 - OFF POSITION
- OFF
- ON
- OFF
- ON
- OFF
- ON
- OFF
- ON
- OFF
- ON
- SET PRSNT TO THE FOLLOWING:
  X16 LANES: PRSNT2_4
   X8 LANES: PRSNT2_3
   X4 LANES: PRSNT2_2
   X1 LANES: PRSNT2_1
sheet 2
- J3 (U1,U2):
  1-2 (ON) FOR 3.3V,
  1-2 (OFF) FOR 2.5V.
  J4 (U1,U2):
  1-2, 3-4 (ON) FOR 2.5V,
  1-2, 3-4 (OFF) FOR
  3.3V.
- J5 (U3,U4):
  1-2 (ON) FOR 3.3V,
  1-2 (OFF) FOR 2.5V.
  J6 (U3,U4):
  1-2, 3-4 (ON) FOR 2.5V,
  1-2, 3-4 (OFF) FOR
  3.3V.
- 9
- PLACE CLOSE TO PIN
- 14
- 36
- 41
- 51
- 9
- PLACE CLOSE TO PIN
- 14
- 36
- 41
- 51
- PLACE CLOSE TO PIN
- PLACE CLOSE TO PIN
- 9
- 14
- 36
- 41
- 51
- 9
- 14
- 36
- 41
- 51
